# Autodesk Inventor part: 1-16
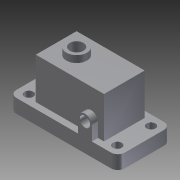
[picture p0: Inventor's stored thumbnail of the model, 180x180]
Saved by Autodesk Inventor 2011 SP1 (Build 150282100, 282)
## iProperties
Created: 2014-02
Part Number: 1-16
Document SubType Name: Modeling
Designer: Administrator
Density: 1 g/cm^3
Author: Administrator
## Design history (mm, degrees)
sketch "草图1"
  geometry: L1 (-15.86, 7.751)-(15.86, 7.751); L2 (15.86, 7.751)-(15.86, -7.751); L3 (15.86, -7.751)-(-15.86, -7.751); L4 (-15.86, -7.751)-(-15.86, 7.751); 3 further points
  constraints: 8 end point, 2 midpoint, 2 parallel, 1 horizontal, 1 horizontal alignment, 1 perpendicular, 1 vertical alignment
extrude "拉伸1" new body sketch "草图1" distance "d0" = 4; taper "d1" = 0 deg
sketch "草图2"
  geometry: L1 (-9.931, 5.952)-(9.994, 5.952); L2 (9.994, 5.952)-(9.994, -5.952); L3 (9.994, -5.952)-(-9.931, -5.952); L4 (-9.931, -5.952)-(-9.931, 5.952); 1 further point
  constraints: 8 end point, 2 parallel, 1 horizontal, 1 perpendicular
extrude "拉伸2" join sketch "草图2" distance "d2" = 12; taper "d3" = 0 deg
sketch "草图3"
  geometry: L1 (-9.994, -5.952)-(9.931, -5.952) reference; L2 (-9.994, 5.952)-(-9.994, -5.952) reference; L3 (9.931, 5.952)-(-9.994, 5.952) reference; L4 (9.931, -5.952)-(9.931, 5.952) reference; L5 (-7.989, -4.012)-(7.989, -4.012); L6 (7.989, -4.012)-(7.989, 4.012); L7 (7.989, 4.012)-(-7.989, 4.012); L8 (-7.989, 4.012)-(-7.989, -4.012); 1 further point
  constraints: 8 end point, 2 parallel, 1 horizontal, 1 perpendicular
extrude "拉伸3" cut sketch "草图3" distance "d4" = 14; taper "d5" = 0 deg
fillet "圆角1" dims "d6" = 2
sketch "草图4"
  geometry: C1 r 1.283 at (-12.925, -4.987); A1 r 2 centre (-13.86, 5.751) between (-13.86, 7.751) and (-15.86, 5.751) reference; 2 further points
  constraints: 1 centre point, 3 other
extrude "拉伸4" cut sketch "草图4" distance "d7" = 14; taper "d8" = 0 deg
mirror "镜像1"
sketch "草图5"
  geometry: L1 (-7.989, -4.012)-(-7.989, 4.012) reference; C1 r 3 at (-3.945, 0); 1 further point
  constraints: 1 centre point
  dimensions: "d9" = 6 diameter of C1
extrude "拉伸5" join sketch "草图5" distance "d10" = 2; taper "d11" = 0 deg
sketch "草图6"
  geometry: C1 r 3 at (0, 0) reference; C2 r 2 at (0, 0); 1 further point
  constraints: 1 centre point, 1 coincident
  dimensions: "d12" = 4 diameter of C2
extrude "拉伸6" cut sketch "草图6" stored distance "d13" = 2; taper "d14" = 0 deg
sketch "草图7"
  geometry: L1 (27.72, 4)-(0, 4) reference; L2 (18.059, 8.018)-(18.059, 4); L3 (22.112, 8.018)-(22.112, 4); A1 r 2.027 centre (20.085, 8.018) between (22.112, 8.018) and (18.059, 8.018); 1 further point
  constraints: 4 end point, 2 perpendicular, 2 point on circle, 2 point on line, 2 tangent, 1 centre point
extrude "拉伸7" join sketch "草图7" stored distance "d15" = 2; taper "d16" = 0 deg
sketch "草图8"
  geometry: C1 r 1.5 at (20.085, 8.018); A1 r 2.027 centre (20.085, 8.018) between (22.112, 8.018) and (18.059, 8.018) reference; 1 further point
  constraints: 1 centre point, 1 coincident
  dimensions: "d17" = 3 diameter of C1
extrude "拉伸8" cut sketch "草图8" stored distance "d18" = 2; taper "d19" = 0 deg
node "实体1"
